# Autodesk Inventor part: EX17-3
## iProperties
Shininess: 64.0
Length Units: 11272
Angle Units: 11279
Time Units: 11290
Mass Units: 11286
Length Display Precision: 3
Compacted: True
Part Number: EX17-3
Document SubType Name: Modeling
Created: 2002-11
Designer: E. MOSS
Project: EVERGREEN VALLEY COLLEGE
Description: PLATE
Authority: MS. TEACHER
Density: 0.0
Volumn: 0.0
Area: 0.0
PropertySet Name: Model Information
Control State: 0
Master: False
Checked Out: False
Author: E. MOSS
Revision Number: A
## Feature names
1. Extrusion1
2. Hole1
